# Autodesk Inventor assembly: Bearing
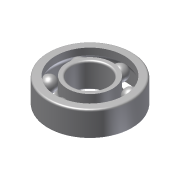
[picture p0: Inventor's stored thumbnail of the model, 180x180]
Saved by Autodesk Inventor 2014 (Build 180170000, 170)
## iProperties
Created: 2011-01
Part Number: Bearing
Document SubType Name: Assembly
Designer: Beta-8540w
ClientObjectVersion: 1
Author: Beta-8540w
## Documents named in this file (2)
- C:\Inventor 2014 Essentials\Assemblies\Chapter 09\Design Accelerators\Bearing c09-02.iam
- C:\Inventor 2014 Essentials\Content Center Files\en-US\SKF B - angular contact\SKF B7204 BE.ipt
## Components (1 placed, 1 different names)
1. SKF B- Angular contact SKF B7204 BE:1
